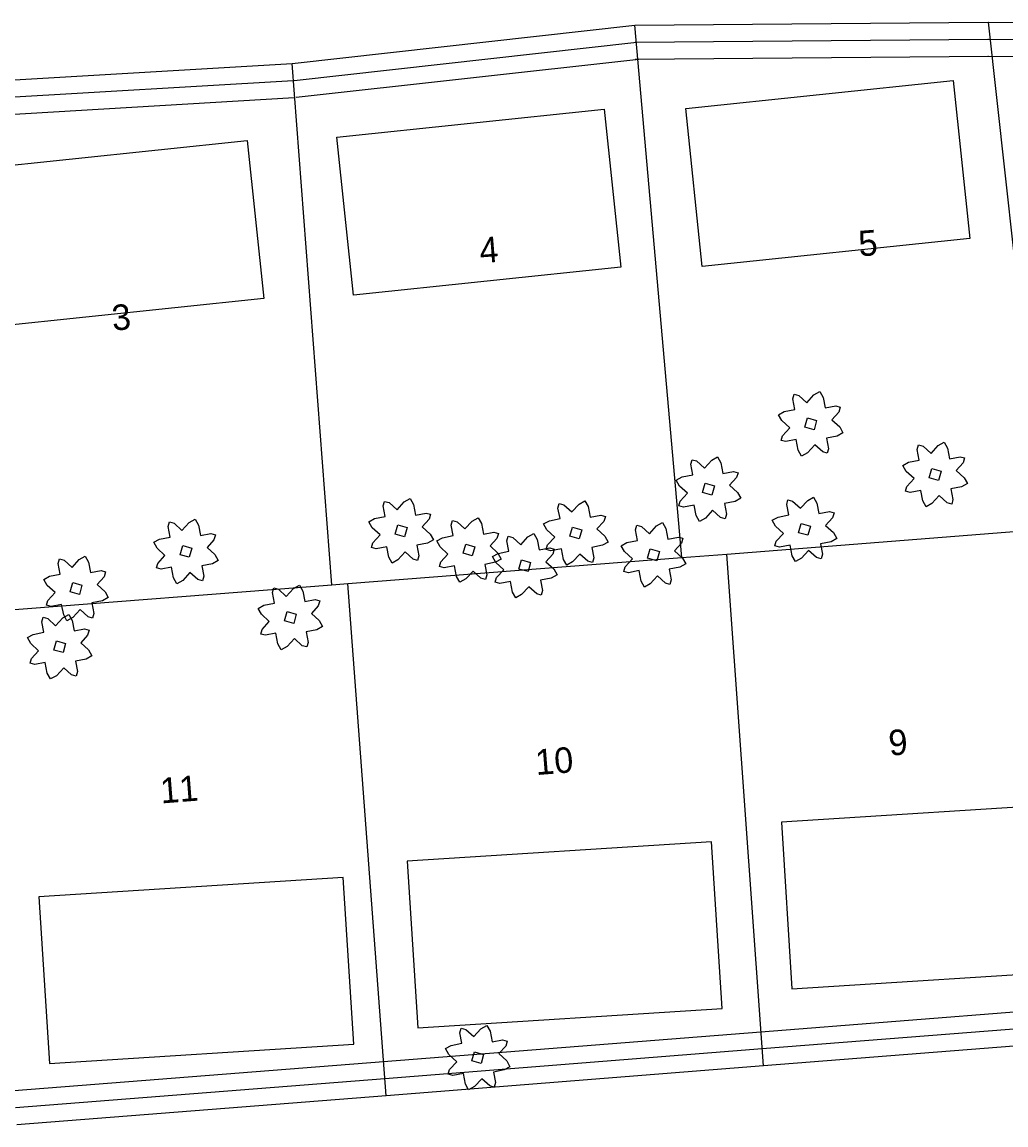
# Model space of a CAD drawing. Extents: x 1810019 to 1811399, y 1074962 to 1076105.
# Drawn here: x 1810242.7 to 1810473.9, y 1074977.1 to 1075236.3 of the extents above; entities that cross this region are included whole.
import ezdxf

# ---------------------------------------------------------------- set-up
doc = ezdxf.new("R2010")
doc.units = 0
for name, color, linetype in [('Environmental-New trees', 7, 'Continuous'), ('Property-Buildings', 7, 'Continuous'), ('Roadway-Land lines', 7, 'Continuous'), ('Roadway-Sidewalks', 7, 'Continuous'), ('Text-Property owner', 7, 'Continuous')]:
    doc.layers.add(name, color=color, linetype=linetype)

msp = doc.modelspace()

# ---------------------------------------------------------------- linework, layer by layer
at = {"layer": 'Environmental-New trees'}
for points in [[(1810421.08, 1075138.03), (1810421.38, 1075139.11), (1810423.08, 1075140.98), (1810421.22, 1075142.67), (1810420.44, 1075144.06), (1810421.79, 1075144.82), (1810424.3, 1075145.31), (1810423.82, 1075147.78), (1810424.13, 1075148.86), (1810425.21, 1075148.56), (1810427.07, 1075146.86), (1810428.77, 1075148.73), (1810430.15, 1075149.5), (1810430.93, 1075148.11), (1810431.41, 1075145.64), (1810433.88, 1075146.12), (1810434.96, 1075145.81), (1810434.59, 1075144.66), (1810432.96, 1075142.87), (1810434.82, 1075141.17), (1810435.6, 1075139.79), (1810434.25, 1075139.03), (1810431.74, 1075138.53), (1810432.21, 1075136.06), (1810431.91, 1075134.98), (1810430.83, 1075135.29), (1810428.96, 1075136.98), (1810427.27, 1075135.12), (1810425.88, 1075134.34), (1810425.1, 1075135.73), (1810424.63, 1075138.2), (1810422.16, 1075137.73)], [(1810427.24, 1075143.31), (1810429.41, 1075142.7), (1810428.8, 1075140.53), (1810426.63, 1075141.14)], [(1810450.31, 1075126.1), (1810450.62, 1075127.19), (1810452.31, 1075129.05), (1810450.45, 1075130.74), (1810449.67, 1075132.13), (1810451.02, 1075132.89), (1810453.53, 1075133.38), (1810453.06, 1075135.85), (1810453.36, 1075136.94), (1810454.45, 1075136.63), (1810456.31, 1075134.94), (1810458, 1075136.8), (1810459.39, 1075137.58), (1810460.17, 1075136.19), (1810460.64, 1075133.72), (1810463.11, 1075134.19), (1810464.19, 1075133.88), (1810463.82, 1075132.73), (1810462.2, 1075130.94), (1810464.06, 1075129.25), (1810464.83, 1075127.86), (1810463.48, 1075127.1), (1810460.97, 1075126.61), (1810461.45, 1075124.14), (1810461.14, 1075123.05), (1810460.06, 1075123.36), (1810458.2, 1075125.05), (1810456.5, 1075123.19), (1810455.12, 1075122.41), (1810454.34, 1075123.8), (1810453.87, 1075126.27), (1810451.39, 1075125.8)], [(1810397.06, 1075122.65), (1810397.37, 1075123.73), (1810399.06, 1075125.59), (1810397.2, 1075127.29), (1810396.42, 1075128.68), (1810397.78, 1075129.43), (1810400.28, 1075129.93), (1810399.81, 1075132.4), (1810400.12, 1075133.48), (1810401.2, 1075133.18), (1810403.06, 1075131.48), (1810404.75, 1075133.34), (1810406.14, 1075134.12), (1810406.92, 1075132.73), (1810407.39, 1075130.26), (1810409.86, 1075130.73), (1810410.95, 1075130.43), (1810410.58, 1075129.27), (1810408.95, 1075127.49), (1810410.81, 1075125.79), (1810411.59, 1075124.4), (1810410.24, 1075123.65), (1810407.73, 1075123.15), (1810408.2, 1075120.68), (1810407.9, 1075119.6), (1810406.81, 1075119.9), (1810404.95, 1075121.6), (1810403.26, 1075119.74), (1810401.87, 1075118.96), (1810401.09, 1075120.35), (1810400.62, 1075122.82), (1810398.15, 1075122.34)], [(1810456.47, 1075131.38), (1810458.64, 1075130.77), (1810458.03, 1075128.61), (1810455.86, 1075129.22)], [(1810403.23, 1075127.93), (1810405.39, 1075127.32), (1810404.78, 1075125.15), (1810402.62, 1075125.76)], [(1810324.81, 1075112.86), (1810325.12, 1075113.94), (1810326.81, 1075115.81), (1810324.95, 1075117.5), (1810324.17, 1075118.89), (1810325.53, 1075119.64), (1810328.03, 1075120.14), (1810327.56, 1075122.61), (1810327.87, 1075123.69), (1810328.95, 1075123.39), (1810330.81, 1075121.69), (1810332.5, 1075123.55), (1810333.89, 1075124.33), (1810334.67, 1075122.94), (1810335.14, 1075120.47), (1810337.61, 1075120.95), (1810338.7, 1075120.64), (1810338.33, 1075119.48), (1810336.7, 1075117.7), (1810338.56, 1075116), (1810339.34, 1075114.61), (1810337.98, 1075113.86), (1810335.48, 1075113.36), (1810335.95, 1075110.89), (1810335.64, 1075109.81), (1810334.56, 1075110.11), (1810332.7, 1075111.81), (1810331.01, 1075109.95), (1810329.62, 1075109.17), (1810328.84, 1075110.56), (1810328.37, 1075113.03), (1810325.9, 1075112.56)], [(1810365.88, 1075112.37), (1810366.18, 1075113.45), (1810367.88, 1075115.31), (1810366.02, 1075117), (1810365.24, 1075118.39), (1810366.59, 1075119.15), (1810369.1, 1075119.64), (1810368.62, 1075122.11), (1810368.93, 1075123.2), (1810370.01, 1075122.89), (1810371.87, 1075121.2), (1810373.57, 1075123.06), (1810374.96, 1075123.84), (1810375.73, 1075122.45), (1810376.21, 1075119.98), (1810378.68, 1075120.45), (1810379.76, 1075120.14), (1810379.39, 1075118.99), (1810377.76, 1075117.2), (1810379.62, 1075115.51), (1810380.4, 1075114.12), (1810379.05, 1075113.36), (1810376.54, 1075112.87), (1810377.01, 1075110.4), (1810376.71, 1075109.31), (1810375.63, 1075109.62), (1810373.76, 1075111.31), (1810372.07, 1075109.45), (1810370.68, 1075108.67), (1810369.91, 1075110.06), (1810369.43, 1075112.53), (1810366.96, 1075112.06)], [(1810419.62, 1075113.22), (1810419.93, 1075114.3), (1810421.62, 1075116.16), (1810419.76, 1075117.86), (1810418.98, 1075119.24), (1810420.33, 1075120), (1810422.84, 1075120.5), (1810422.37, 1075122.97), (1810422.67, 1075124.05), (1810423.76, 1075123.74), (1810425.62, 1075122.05), (1810427.31, 1075123.91), (1810428.7, 1075124.69), (1810429.48, 1075123.3), (1810429.95, 1075120.83), (1810432.42, 1075121.3), (1810433.5, 1075121), (1810433.14, 1075119.84), (1810431.51, 1075118.05), (1810433.37, 1075116.36), (1810434.14, 1075114.97), (1810432.79, 1075114.21), (1810430.29, 1075113.72), (1810430.76, 1075111.25), (1810430.45, 1075110.17), (1810429.37, 1075110.47), (1810427.51, 1075112.17), (1810425.82, 1075110.3), (1810424.43, 1075109.53), (1810423.65, 1075110.92), (1810423.18, 1075113.39), (1810420.7, 1075112.91)], [(1810340.77, 1075108.37), (1810341.07, 1075109.45), (1810342.77, 1075111.31), (1810340.9, 1075113), (1810340.13, 1075114.39), (1810341.48, 1075115.15), (1810343.99, 1075115.64), (1810343.51, 1075118.11), (1810343.82, 1075119.2), (1810344.9, 1075118.89), (1810346.76, 1075117.2), (1810348.46, 1075119.06), (1810349.84, 1075119.84), (1810350.62, 1075118.45), (1810351.1, 1075115.98), (1810353.57, 1075116.45), (1810354.65, 1075116.15), (1810354.28, 1075114.99), (1810352.65, 1075113.2), (1810354.51, 1075111.51), (1810355.29, 1075110.12), (1810353.94, 1075109.36), (1810351.43, 1075108.87), (1810351.9, 1075106.4), (1810351.6, 1075105.32), (1810350.51, 1075105.62), (1810348.65, 1075107.31), (1810346.96, 1075105.45), (1810345.57, 1075104.67), (1810344.79, 1075106.06), (1810344.32, 1075108.53), (1810341.85, 1075108.06)], [(1810274.26, 1075108.03), (1810274.56, 1075109.12), (1810276.25, 1075110.98), (1810274.39, 1075112.67), (1810273.61, 1075114.06), (1810274.97, 1075114.82), (1810277.47, 1075115.31), (1810277, 1075117.78), (1810277.31, 1075118.87), (1810278.39, 1075118.56), (1810280.25, 1075116.87), (1810281.94, 1075118.73), (1810283.33, 1075119.51), (1810284.11, 1075118.12), (1810284.58, 1075115.65), (1810287.05, 1075116.12), (1810288.14, 1075115.81), (1810287.77, 1075114.66), (1810286.14, 1075112.87), (1810288, 1075111.18), (1810288.78, 1075109.79), (1810287.43, 1075109.03), (1810284.92, 1075108.54), (1810285.39, 1075106.07), (1810285.09, 1075104.98), (1810284, 1075105.29), (1810282.14, 1075106.98), (1810280.45, 1075105.12), (1810279.06, 1075104.34), (1810278.28, 1075105.73), (1810277.81, 1075108.2), (1810275.34, 1075107.73)], [(1810330.98, 1075118.14), (1810333.14, 1075117.53), (1810332.53, 1075115.36), (1810330.37, 1075115.97)], [(1810372.04, 1075117.64), (1810374.21, 1075117.03), (1810373.6, 1075114.87), (1810371.43, 1075115.48)], [(1810384.11, 1075107.23), (1810384.42, 1075108.31), (1810386.11, 1075110.17), (1810384.25, 1075111.87), (1810383.47, 1075113.25), (1810384.82, 1075114.01), (1810387.33, 1075114.51), (1810386.86, 1075116.98), (1810387.16, 1075118.06), (1810388.24, 1075117.75), (1810390.11, 1075116.06), (1810391.8, 1075117.92), (1810393.19, 1075118.7), (1810393.97, 1075117.31), (1810394.44, 1075114.84), (1810396.91, 1075115.31), (1810397.99, 1075115.01), (1810397.62, 1075113.85), (1810395.99, 1075112.06), (1810397.86, 1075110.37), (1810398.63, 1075108.98), (1810397.28, 1075108.22), (1810394.77, 1075107.73), (1810395.25, 1075105.26), (1810394.94, 1075104.18), (1810393.86, 1075104.48), (1810392, 1075106.18), (1810390.3, 1075104.31), (1810388.92, 1075103.54), (1810388.14, 1075104.93), (1810387.66, 1075107.4), (1810385.19, 1075106.92)], [(1810425.79, 1075118.5), (1810427.95, 1075117.89), (1810427.34, 1075115.72), (1810425.17, 1075116.33)], [(1810353.87, 1075104.67), (1810354.18, 1075105.76), (1810355.87, 1075107.62), (1810354.01, 1075109.31), (1810353.23, 1075110.7), (1810354.58, 1075111.46), (1810357.09, 1075111.95), (1810356.62, 1075114.42), (1810356.92, 1075115.51), (1810358.01, 1075115.2), (1810359.87, 1075113.51), (1810361.56, 1075115.37), (1810362.95, 1075116.15), (1810363.73, 1075114.76), (1810364.2, 1075112.29), (1810366.67, 1075112.76), (1810367.75, 1075112.45), (1810367.38, 1075111.3), (1810365.76, 1075109.51), (1810367.62, 1075107.82), (1810368.39, 1075106.43), (1810367.04, 1075105.67), (1810364.53, 1075105.18), (1810365.01, 1075102.71), (1810364.7, 1075101.62), (1810363.62, 1075101.93), (1810361.76, 1075103.62), (1810360.06, 1075101.76), (1810358.68, 1075100.98), (1810357.9, 1075102.37), (1810357.43, 1075104.84), (1810354.95, 1075104.37)], [(1810280.42, 1075113.31), (1810282.58, 1075112.7), (1810281.97, 1075110.54), (1810279.81, 1075111.15)], [(1810346.93, 1075113.64), (1810349.1, 1075113.03), (1810348.49, 1075110.87), (1810346.32, 1075111.48)], [(1810390.27, 1075112.51), (1810392.44, 1075111.9), (1810391.83, 1075109.73), (1810389.66, 1075110.34)], [(1810248.43, 1075099.32), (1810248.73, 1075100.4), (1810250.43, 1075102.26), (1810248.57, 1075103.95), (1810247.79, 1075105.34), (1810249.14, 1075106.1), (1810251.65, 1075106.59), (1810251.18, 1075109.06), (1810251.48, 1075110.15), (1810252.56, 1075109.84), (1810254.43, 1075108.15), (1810256.12, 1075110.01), (1810257.51, 1075110.79), (1810258.28, 1075109.4), (1810258.76, 1075106.93), (1810261.23, 1075107.4), (1810262.31, 1075107.09), (1810261.94, 1075105.94), (1810260.31, 1075104.15), (1810262.17, 1075102.46), (1810262.95, 1075101.07), (1810261.6, 1075100.31), (1810259.09, 1075099.82), (1810259.57, 1075097.35), (1810259.26, 1075096.26), (1810258.18, 1075096.57), (1810256.32, 1075098.26), (1810254.62, 1075096.4), (1810253.23, 1075095.62), (1810252.46, 1075097.01), (1810251.98, 1075099.48), (1810249.51, 1075099.01)], [(1810360.03, 1075109.95), (1810362.2, 1075109.34), (1810361.59, 1075107.18), (1810359.42, 1075107.79)], [(1810254.59, 1075104.59), (1810256.76, 1075103.98), (1810256.15, 1075101.82), (1810253.98, 1075102.43)], [(1810298.79, 1075092.51), (1810299.09, 1075093.59), (1810300.78, 1075095.45), (1810298.92, 1075097.15), (1810298.15, 1075098.54), (1810299.5, 1075099.29), (1810302.01, 1075099.79), (1810301.53, 1075102.26), (1810301.84, 1075103.34), (1810302.92, 1075103.04), (1810304.78, 1075101.34), (1810306.47, 1075103.2), (1810307.86, 1075103.98), (1810308.64, 1075102.59), (1810309.11, 1075100.12), (1810311.59, 1075100.59), (1810312.67, 1075100.29), (1810312.3, 1075099.13), (1810310.67, 1075097.35), (1810312.53, 1075095.65), (1810313.31, 1075094.26), (1810311.96, 1075093.51), (1810309.45, 1075093.01), (1810309.92, 1075090.54), (1810309.62, 1075089.46), (1810308.53, 1075089.76), (1810306.67, 1075091.46), (1810304.98, 1075089.6), (1810303.59, 1075088.82), (1810302.81, 1075090.21), (1810302.34, 1075092.68), (1810299.87, 1075092.21)], [(1810244.58, 1075085.64), (1810244.88, 1075086.72), (1810246.57, 1075088.58), (1810244.71, 1075090.27), (1810243.94, 1075091.66), (1810245.29, 1075092.42), (1810247.79, 1075092.91), (1810247.32, 1075095.38), (1810247.63, 1075096.47), (1810248.71, 1075096.16), (1810250.57, 1075094.47), (1810252.26, 1075096.33), (1810253.65, 1075097.11), (1810254.43, 1075095.72), (1810254.9, 1075093.25), (1810257.38, 1075093.72), (1810258.46, 1075093.42), (1810258.09, 1075092.26), (1810256.46, 1075090.47), (1810258.32, 1075088.78), (1810259.1, 1075087.39), (1810257.75, 1075086.63), (1810255.24, 1075086.14), (1810255.71, 1075083.67), (1810255.41, 1075082.58), (1810254.32, 1075082.89), (1810252.46, 1075084.58), (1810250.77, 1075082.72), (1810249.38, 1075081.94), (1810248.6, 1075083.33), (1810248.13, 1075085.8), (1810245.66, 1075085.33)], [(1810304.95, 1075097.79), (1810307.12, 1075097.18), (1810306.51, 1075095.01), (1810304.34, 1075095.62)], [(1810250.74, 1075090.91), (1810252.91, 1075090.3), (1810252.3, 1075088.14), (1810250.13, 1075088.75)], [(1810342.82, 1074989.05), (1810343.13, 1074990.14), (1810344.82, 1074992), (1810342.96, 1074993.69), (1810342.18, 1074995.08), (1810343.53, 1074995.84), (1810346.04, 1074996.33), (1810345.57, 1074998.8), (1810345.87, 1074999.89), (1810346.96, 1074999.58), (1810348.82, 1074997.89), (1810350.51, 1074999.75), (1810351.9, 1075000.53), (1810352.68, 1074999.14), (1810353.15, 1074996.67), (1810355.62, 1074997.14), (1810356.7, 1074996.83), (1810356.33, 1074995.68), (1810354.71, 1074993.89), (1810356.57, 1074992.2), (1810357.34, 1074990.81), (1810355.99, 1074990.05), (1810353.48, 1074989.56), (1810353.96, 1074987.09), (1810353.65, 1074986), (1810352.57, 1074986.31), (1810350.71, 1074988), (1810349.01, 1074986.14), (1810347.63, 1074985.36), (1810346.85, 1074986.75), (1810346.38, 1074989.22), (1810343.9, 1074988.75)], [(1810348.98, 1074994.33), (1810351.15, 1074993.72), (1810350.54, 1074991.56), (1810348.37, 1074992.17)]]:
    msp.add_lwpolyline(points, close=True, dxfattribs=at)
at = {"layer": 'Property-Buildings'}
for points in [[(1810398.65, 1075216), (1810461.48, 1075222.58), (1810465.37, 1075185.45), (1810402.54, 1075178.87)], [(1810316.66, 1075209.27), (1810379.49, 1075215.85), (1810383.38, 1075178.73), (1810320.55, 1075172.14)], [(1810232.74, 1075201.92), (1810295.57, 1075208.5), (1810299.46, 1075171.37), (1810236.63, 1075164.79)], [(1810423.6, 1075009.1), (1810495.11, 1075013.64), (1810492.63, 1075052.82), (1810421.12, 1075048.28)], [(1810335.67, 1074999.95), (1810407.18, 1075004.49), (1810404.69, 1075043.67), (1810333.18, 1075039.13)], [(1810249.13, 1074991.59), (1810320.64, 1074996.12), (1810318.15, 1075035.3), (1810246.64, 1075030.76)]]:
    msp.add_lwpolyline(points, close=True, dxfattribs=at)
at = {"layer": 'Roadway-Land lines'}
for p, q in [((1810386.7, 1075235.57), (1810469.69, 1075236.34)), ((1810469.69, 1075236.34), (1810469.79, 1075236.34)), ((1810482.93, 1075117.14), (1810469.79, 1075236.34)), ((1810306.17, 1075226.61), (1810386.7, 1075235.57)), ((1810397.74, 1075110.49), (1810386.7, 1075235.57)), ((1810220.99, 1075221.55), (1810306.17, 1075226.61)), ((1810315.51, 1075104.07), (1810306.17, 1075226.61)), ((1810408.27, 1075111.31), (1810482.93, 1075117.14)), ((1810319.22, 1075104.36), (1810397.74, 1075110.49)), ((1810397.74, 1075110.49), (1810408.27, 1075111.31)), ((1810416.91, 1074990.99), (1810408.27, 1075111.31)), ((1810231.65, 1075097.52), (1810315.51, 1075104.07)), ((1810315.51, 1075104.07), (1810319.22, 1075104.36)), ((1810328.22, 1074983.99), (1810319.22, 1075104.36)), ((1810503.65, 1074997.84), (1810416.91, 1074990.99)), ((1810416.91, 1074990.99), (1810328.22, 1074983.99)), ((1810328.22, 1074983.99), (1810241.42, 1074977.13))]:
    msp.add_line(p, q, dxfattribs=at)
msp.add_lwpolyline([(1810469.79, 1075236.34), (1810491.37, 1075236.13), (1810513.03, 1075235.16), (1810534.65, 1075233.45), (1810556.2, 1075230.98), (1810576.73, 1075227.91)], dxfattribs=at)
at = {"layer": 'Roadway-Sidewalks'}
for p, q in [((1810306.62, 1075222.64), (1810387.14, 1075231.6)), ((1810386.74, 1075231.58), (1810469.72, 1075232.34)), ((1810469.65, 1075232.34), (1810469.76, 1075232.34)), ((1810307.06, 1075218.66), (1810387.59, 1075227.62)), ((1810386.78, 1075227.58), (1810469.76, 1075228.34)), ((1810469.61, 1075228.34), (1810469.72, 1075228.34)), ((1810221.23, 1075217.56), (1810306.41, 1075222.62)), ((1810221.47, 1075213.56), (1810306.65, 1075218.63)), ((1810503.02, 1075005.82), (1810416.28, 1074998.97)), ((1810503.33, 1075001.83), (1810416.6, 1074994.98)), ((1810416.28, 1074998.97), (1810327.59, 1074991.96)), ((1810416.6, 1074994.98), (1810327.91, 1074987.98)), ((1810327.59, 1074991.96), (1810240.79, 1074985.11)), ((1810327.91, 1074987.98), (1810241.1, 1074981.12))]:
    msp.add_line(p, q, dxfattribs=at)
for points in [[(1810469.76, 1075232.34), (1810491.26, 1075232.13), (1810512.79, 1075231.17), (1810534.27, 1075229.47), (1810555.67, 1075227.01), (1810576.14, 1075223.95)], [(1810469.72, 1075228.34), (1810491.15, 1075228.13), (1810512.54, 1075227.18), (1810533.88, 1075225.48), (1810555.15, 1075223.05), (1810575.54, 1075219.99)]]:
    msp.add_lwpolyline(points, dxfattribs=at)

# ---------------------------------------------------------------- texts
at = {"layer": 'Text-Property owner'}
for s, p in [('5', (1810439.47, 1075181.24)), ('4', (1810350.38, 1075179.65)), ('3', (1810264, 1075163.81)), ('9', (1810446.54, 1075063.9)), ('10', (1810363.52, 1075059.35)), ('11', (1810275.37, 1075052.68))]:
    msp.add_text(s, height=6, rotation=4.4642, dxfattribs=at).set_placement(p)

doc.saveas('drawing.dxf')
